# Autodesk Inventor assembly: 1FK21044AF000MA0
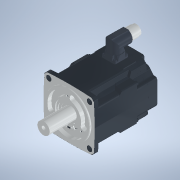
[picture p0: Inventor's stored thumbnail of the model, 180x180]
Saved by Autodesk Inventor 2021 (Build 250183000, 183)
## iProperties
Category: PARTsolutions
Created: 2026-06
Part Number: 1FK21044AF000MA0
Catalog Web Link: www.3dfindit.com
Description: 1FK21044AF000MA0-Servo synchronous motor
Document SubType Name: Assembly
Designer: psAdmin
Mass: 565.652 g
Surface Area: 988.094 cm^2
Volume: 565.652 cm^3
Density: 1 g/cm^3
Title: 1FK21044AF000MA0
Author: Cadenas PARTsolutions
Comments: Servo synchronous motor
PSOL_IDENT_0: {$CADENAS_DATA/23d-libs/siemens_ag/_cat_/39/c4/1fk21044af000ma0.prj},193 {STYP=ASS},{VTYP=3D},{NB=1F
PSOL_IDENT_1: K21044AF000MA0},{LINA=1FK21044AF000MA0},{NN=1FK21044AF000MA0},{DATE=19.08.2025 14:00:33},{GEOMDATE=3
PSOL_IDENT_2: 0.07.2025 02:02:22},{VERSION=},{LINEID=10},{WBVAR=},{WBNUMERIC=}  {NB=1FK21044AF000MA0},{LINA=1FK210
PSOL_IDENT_3: 44AF000MA0},{KT=DUMMY},{PREVIEW=../../../_pool_/cb/72/p_d211_xx_00434j.png},{DESCSHORT=SIMOTICS S-1F
PSOL_IDENT_4: K2 HD, SINAMICS S210 3AC 400V-480V, 1.27 Nm, 3000 rpm},{DESCLONG=SIMOTICS S-1FK2 HD servo motor M0=1
PSOL_IDENT_5: .27 Nm; PN = 0.4 kW at nN=3000 rpm (380-480 V); PN = 0.2 kW at nN=1500 rpm (200-240 V); degree of pr
PSOL_IDENT_6: otection IP64; cylindrical shaft D19x40mm; absolute encoder 22-bit + 12-bit multiturn (encoder AM22D
PSOL_IDENT_7: QC); with OCC interface; plug size M17, rotatable; SIMOTICS S-1FK2 servomotorfor a wide range of use
PSOL_IDENT_8: s in industrial environments. SIMOTICS S‑1FK2 servomotors are compact synchronous motors with a high
PSOL_IDENT_9: dynamic performance that set themselves apart as a result of their high power density, degree of pr
PSOL_IDENT_10: otection and overload capability. The motors are available in two variants: as High Dynamic variant
PSOL_IDENT_11: (highest dynamic performance as a result of the low intrinsic moment of inertia for applications dem
PSOL_IDENT_12: anding a high dynamic performance with low moved masses) - and as Compact variant (precise and stabl
PSOL_IDENT_13: e closed-loop control for medium up to large moved masses as a result of a medium intrinsic moment o
PSOL_IDENT_14: f inertia). SIMOTICSS‑1FK2 servomotors fully exploit their strengths in a system with the SINAMICSS2
PSOL_IDENT_15: 10 frequency converter and simple connection using the one cable connection (OCC). Advantages includ
PSOL_IDENT_16: e the short control and positioning times, fast and precise correction of disturbing quantities as w
PSOL_IDENT_17: ell as stable control with a high dynamic performance. The servo motors can be configured to address
PSOL_IDENT_18: a wide range of requirements. For example with and without holding brake, IP64 or IP65 degree of pr
PSOL_IDENT_19: otection, singleturn or multiturn absolute encoders - to name just a few. Further, the servomotors a
PSOL_IDENT_20: re available in different shaft heights extending from 20 to 100. A shaft sealing ring is available
PSOL_IDENT_21: to achieve an IP65 degree of protection and for subsequent mounting at the motor or as spare part. S
PSOL_IDENT_22: IMOTICS - the optimum motor for each and every motion control application.},{INTNO=804766906428},{SU
PSOL_IDENT_23: PPLIERALTNO=1FK2104-4AF00-0MA0},{MANUID=1FK21044AF000MA0},{MANUNAME=Siemens},{MANUTYPEDESC=Synchrono
PSOL_IDENT_24: us motor 1FK2-HD 1.27 NM},{AAU732=SIMOTICS},{AAO057=S-1FK2},{AAU734=SIMOTICS S-1FK2 HD servo motor M
PSOL_IDENT_25: 0=1.27 Nm; PN = 0.4 kW at nN=3000 rpm (380-480 V); PN = 0.2 kW at nN=1500 rpm (200-240 V); degree of
PSOL_IDENT_26: protection IP64; cylindrical shaft D19x40mm; absolute encoder 22-bit + 12-bit multiturn (encoder AM
PSOL_IDENT_27: 22DQC); with OCC interface; plug size M17, rotatable;},{AAW338=Synchronous motor 1FK2-HD 1.27 NM},{A
PSOL_IDENT_28: AO742=SIMOTICS},{AAO663=4042948693322},{NOCUPEROU=1},{PRICEQUANTITY=1},{QUANTITYMIN=1},{QUANTITYINT=
PSOL_IDENT_29: 1},{CTN=85015100},{COO=DE},{AAO676=1FK2104-4AF00-0MA0},{AAO677=Siemens AG},{ORDERUNIT=C62},{CONTENTU
PSOL_IDENT_30: NIT=C62}
NB: 1FK21044AF000MA0
NN: 1FK21044AF000MA0
NT: Servo synchronous motor
NBSYN: $MANUID.
LINA: 1FK21044AF000MA0
CATALOG: SIEMENS
PREVIEW: ../../../_pool_/cb/72/p_d211_xx_00434j.png
DESCSHORT: SIMOTICS S-1FK2 HD, SINAMICS S210 3AC 400V-480V, 1.27 Nm, 3000 rpm
DESCLONG: SIMOTICS S-1FK2 HD servo motor M0=1.27 Nm; PN = 0.4 kW at nN=3000 rpm (380-480 V); PN = 0.2 kW at nN=1500 rpm (200-240 V); degree of protection IP64; cylindrica
INTNO: 804766906428
SUPPLIERALTNO: 1FK2104-4AF00-0MA0
MANUID: 1FK21044AF000MA0
MANUNAME: Siemens
MANUTYPEDESC: Synchronous motor 1FK2-HD 1.27 NM
AAU732: SIMOTICS
AAO057: S-1FK2
AAU734: SIMOTICS S-1FK2 HD servo motor M0=1.27 Nm; PN = 0.4 kW at nN=3000 rpm (380-480 V); PN = 0.2 kW at nN=1500 rpm (200-240 V); degree of protection IP64; cylindrica
AAW338: Synchronous motor 1FK2-HD 1.27 NM
AAO742: SIMOTICS
AAO663: 4042948693322.0
NOCUPEROU: 1
PRICEQUANTITY: 1
QUANTITYMIN: 1
QUANTITYINT: 1
CTN: 85015100
COO: DE
ARTICLENO: 1FK21044AF000MA0
BOMINFO: 1FK21044AF000MA0
CREATOR: CADENAS GmbH
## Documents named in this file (24)
- e:\temp\worker_COMMON_20\temp\tmp_1756_8_C6W7R\format_0\1FK21044AF000MA0.iam
- e:\temp\worker_COMMON_20\temp\tmp_1756_8_C6W7R\format_0\1FK21044AF000MA0_PART1.ipt
- e:\temp\worker_COMMON_20\temp\tmp_1756_8_C6W7R\format_0\1FK21044AF000MA0_PART2.ipt
- e:\temp\worker_COMMON_20\temp\tmp_1756_8_C6W7R\format_0\1FK21044AF000MA0_PART3.ipt
- e:\temp\worker_COMMON_20\temp\tmp_1756_8_C6W7R\format_0\1FK21044AF000MA0_PART4.ipt
- e:\temp\worker_COMMON_20\temp\tmp_1756_8_C6W7R\format_0\1FK21044AF000MA0_PART5.ipt
- e:\temp\worker_COMMON_20\temp\tmp_1756_8_C6W7R\format_0\1FK21044AF000MA0_PART6.ipt
- e:\temp\worker_COMMON_20\temp\tmp_1756_8_C6W7R\format_0\1FK21044AF000MA0_PART7.ipt
- e:\temp\worker_COMMON_20\temp\tmp_1756_8_C6W7R\format_0\1FK21044AF000MA0_PART8.ipt
- e:\temp\worker_COMMON_20\temp\tmp_1756_8_C6W7R\format_0\1FK21044AF000MA0_PART9.ipt
- e:\temp\worker_COMMON_20\temp\tmp_1756_8_C6W7R\format_0\1FK21044AF000MA0_PART10.ipt
- e:\temp\worker_COMMON_20\temp\tmp_1756_8_C6W7R\format_0\1FK21044AF000MA0_PART11.ipt
- e:\temp\worker_COMMON_20\temp\tmp_1756_8_C6W7R\format_0\1FK21044AF000MA0_PART12.ipt
- e:\temp\worker_COMMON_20\temp\tmp_1756_8_C6W7R\format_0\1FK21044AF000MA0_PART13.ipt
- e:\temp\worker_COMMON_20\temp\tmp_1756_8_C6W7R\format_0\1FK21044AF000MA0_PART14.ipt
- e:\temp\worker_COMMON_20\temp\tmp_1756_8_C6W7R\format_0\1FK21044AF000MA0_PART15.ipt
- e:\temp\worker_COMMON_20\temp\tmp_1756_8_C6W7R\format_0\1FK21044AF000MA0_PART16.ipt
- e:\temp\worker_COMMON_20\temp\tmp_1756_8_C6W7R\format_0\1FK21044AF000MA0_PART17.ipt
- e:\temp\worker_COMMON_20\temp\tmp_1756_8_C6W7R\format_0\1FK21044AF000MA0_PART18.ipt
- e:\temp\worker_COMMON_20\temp\tmp_1756_8_C6W7R\format_0\1FK21044AF000MA0_PART19.ipt
- e:\temp\worker_COMMON_20\temp\tmp_1756_8_C6W7R\format_0\1FK21044AF000MA0_PART20.ipt
- e:\temp\worker_COMMON_20\temp\tmp_1756_8_C6W7R\format_0\1FK21044AF000MA0_PART21.ipt
- e:\temp\worker_COMMON_20\temp\tmp_1756_8_C6W7R\format_0\1FK21044AF000MA0_PART22.ipt
- e:\temp\worker_COMMON_20\temp\tmp_1756_8_C6W7R\format_0\1FK21044AF000MA0_PART23.ipt
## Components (23 placed, 23 different names)
1. 1FK21044AF000MA0_PART1:1
2. 1FK21044AF000MA0_PART2:1
3. 1FK21044AF000MA0_PART3:1
4. 1FK21044AF000MA0_PART4:1
5. 1FK21044AF000MA0_PART5:1
6. 1FK21044AF000MA0_PART6:1
7. 1FK21044AF000MA0_PART7:1
8. 1FK21044AF000MA0_PART8:1
9. 1FK21044AF000MA0_PART9:1
10. 1FK21044AF000MA0_PART10:1
11. 1FK21044AF000MA0_PART11:1
12. 1FK21044AF000MA0_PART12:1
13. 1FK21044AF000MA0_PART13:1
14. 1FK21044AF000MA0_PART14:1
15. 1FK21044AF000MA0_PART15:1
16. 1FK21044AF000MA0_PART16:1
17. 1FK21044AF000MA0_PART17:1
18. 1FK21044AF000MA0_PART18:1
19. 1FK21044AF000MA0_PART19:1
20. 1FK21044AF000MA0_PART20:1
21. 1FK21044AF000MA0_PART21:1
22. 1FK21044AF000MA0_PART22:1
23. 1FK21044AF000MA0_PART23:1
